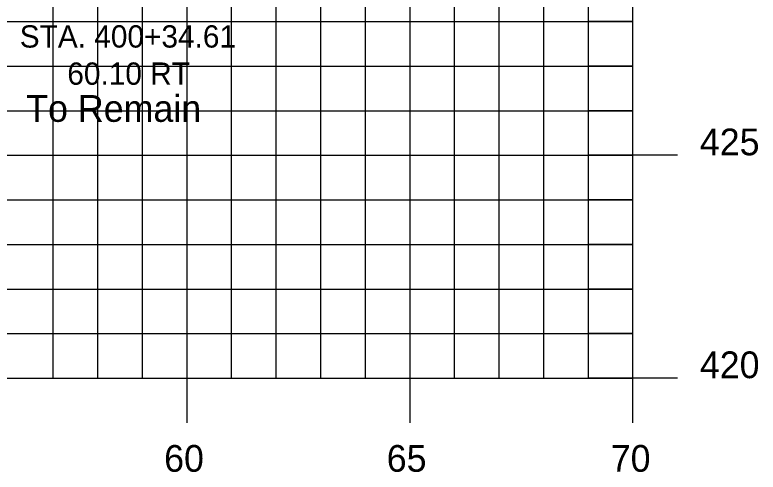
# Model space of a CAD drawing. Extents: x -161 to 764, y 111 to 210.
# Drawn here: x -31.55 to -14.89, y 176.32 to 186.58 of the extents above; entities that cross this region are included whole.
import ezdxf

# ---------------------------------------------------------------- set-up
doc = ezdxf.new("R2010")
doc.units = 0
for name, color, linetype in [('D_Text_Monospaced', 7, 'Continuous'), ('D_Text_Standard', 7, 'Continuous'), ('H_V ANNOTATION', 7, 'Continuous'), ('MAJOR', 7, 'Continuous'), ('MINOR', 7, 'Continuous')]:
    doc.layers.add(name, color=color, linetype=linetype)

msp = doc.modelspace()

# ---------------------------------------------------------------- linework, layer by layer
at = {"layer": 'MAJOR'}
for p, q in [((-27.693, 178.433), (-27.693, 198.433)), ((-22.693, 178.433), (-22.693, 198.433)), ((-17.693, 178.433), (-17.693, 198.433)), ((-17.693, 178.433), (-17.693, 198.433)), ((-157.693, 183.433), (-17.693, 183.433)), ((-16.691, 183.433), (-18.695, 183.433)), ((-157.693, 178.433), (-17.693, 178.433)), ((-157.693, 178.433), (-17.693, 178.433)), ((-27.693, 177.431), (-27.693, 178.433)), ((-22.693, 177.431), (-22.693, 178.433)), ((-16.691, 178.433), (-18.695, 178.433)), ((-17.693, 177.431), (-17.693, 178.433))]:
    msp.add_line(p, q, dxfattribs=at)
at = {"layer": 'MINOR'}
for p, q in [((-30.693, 178.433), (-30.693, 198.433)), ((-29.693, 178.433), (-29.693, 198.433)), ((-28.693, 178.433), (-28.693, 198.433)), ((-26.693, 178.433), (-26.693, 198.433)), ((-25.693, 178.433), (-25.693, 198.433)), ((-24.693, 178.433), (-24.693, 198.433)), ((-23.693, 178.433), (-23.693, 198.433)), ((-21.693, 178.433), (-21.693, 198.433)), ((-20.693, 178.433), (-20.693, 198.433)), ((-19.693, 178.433), (-19.693, 198.433)), ((-18.693, 178.433), (-18.693, 198.433)), ((-157.693, 186.433), (-17.693, 186.433)), ((-17.693, 186.433), (-18.695, 186.433)), ((-157.693, 185.433), (-17.693, 185.433)), ((-17.693, 185.433), (-18.695, 185.433)), ((-157.693, 184.433), (-17.693, 184.433)), ((-17.693, 184.433), (-18.695, 184.433)), ((-157.693, 182.433), (-17.693, 182.433)), ((-17.693, 182.433), (-18.695, 182.433)), ((-157.693, 181.433), (-17.693, 181.433)), ((-17.693, 181.433), (-18.695, 181.433)), ((-157.693, 180.433), (-17.693, 180.433)), ((-17.693, 180.433), (-18.695, 180.433)), ((-157.693, 179.433), (-17.693, 179.433)), ((-17.693, 179.433), (-18.695, 179.433))]:
    msp.add_line(p, q, dxfattribs=at)

# ---------------------------------------------------------------- texts
at = {"layer": 'D_Text_Monospaced'}
for s, height, p in [('STA. 400+34.61', 0.49998, (-31.445, 185.85)), ('60.10 RT', 0.5, (-30.378, 185.016))]:
    msp.add_text(s, height=height, dxfattribs=at).set_placement(p)
at = {"layer": 'D_Text_Standard'}
msp.add_text('To Remain', height=0.6, dxfattribs=at).set_placement((-31.3, 184.184))
at = {"layer": 'H_V ANNOTATION'}
for s, p in [('425', (-16.193, 183.433)), ('420', (-16.193, 178.433)), ('60', (-28.207, 176.333)), ('65', (-23.215, 176.333)), ('70', (-18.191, 176.333))]:
    msp.add_text(s, height=0.6, rotation=360, dxfattribs=at).set_placement(p)

doc.saveas('drawing.dxf')
